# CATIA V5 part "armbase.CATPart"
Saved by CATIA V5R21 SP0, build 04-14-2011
Part number: armbase
Bounding box of the stored display mesh (mm): x -36 to 36, y -57.294 to 35, z 0 to 84.554
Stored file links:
  F:\教程\Robotic_Arm_Arduino_Kinect\机械臂CAD\Arm_Detailed_Design\armbase.CATPart
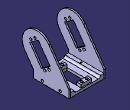
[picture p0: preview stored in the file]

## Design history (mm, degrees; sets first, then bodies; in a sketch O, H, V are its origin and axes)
Body1 (main body)
  Sketch1 on zx-plane, origin (0, 0, 0), H (-1, 0, 0), V (0, 0, 1)
    point P1 (-33, 0)
    line L1 (-33, 0) -> (-33, 9)
    point P2 (-33, 9)
    line L2 (-33, 9) -> (-26, 9)
    point P3 (-26, 9)
    line L3 (-26, 9) -> (-26, 5)
    point P4 (-26, 5)
    line L4 (-26, 5) -> (0, 5)
    point P5 (0, 5)
    line L5 (-33, 0) -> (0, 0)
    point P6 (0, 5)
    point P7 (26, 5)
    line L6 (26, 5) -> (0, 5)
    point P8 (26, 9)
    line L7 (26, 9) -> (26, 5)
    point P9 (33, 9)
    line L8 (33, 9) -> (26, 9)
    point P10 (33, 0)
    line L9 (33, 0) -> (33, 9)
    point P11 (0, 0)
    line L10 (33, 0) -> (0, 0)
    length L5 = 33
    distance L4 L5 = 5
    distance L2 L4 = 4
    length L2 = 7
    coincidence: P1 H, P5 V, O P11, P5 P6
    vertical: L1 V, L3 V
    horizontal: L2 H, L4 H, L5 H
    symmetry: P5 P6 V, P4 P7 V, L4 L6 V, P3 P8 V, L3 L7 V, P2 P9 V, L2 L8 V, P1 P10 V, L1 L9 V, O P11 V, L5 L10 V
  Pad1: profile Sketch1, direction (0, 1, 0), length 35, mirrored extent
  Fillet1: radius 4, on edge [face of Pad1 from Sketch1.L3 | face of Pad1 from Sketch1.L4]; edge [face of Pad1 from Sketch1.L6 | face of Pad1 from Sketch1.L7]
  Sketch2 on face of Pad1 from Sketch1.L6, origin (0, 0, 5), H (1, 0, 0), V (0, 1, 0)
    line L1 (-10.5, 25) -> (10.5, 25)
    line L2 (10.5, 25) -> (10.5, -15.5)
    line L3 (10.5, -15.5) -> (-10.5, -15.5)
    line L4 (-10.5, -15.5) -> (-10.5, 25)
    circle A1 centre (-5, 29) radius 2.5
    point P5 (-5, 29)
    circle A2 centre (5, 29) radius 2.5
    point P6 (5, 29)
    circle A3 centre (-5, -19.5) radius 2.5
    point P7 (-5, -19.5)
    circle A4 centre (5, -19.5) radius 2.5
    point P8 (5, -19.5)
    construction circle A5 centre (0, 15.34) radius 2.8695
    point P9 (0, 15.34)
    axis line L5 (-19.0638, 15.34) -> (25.8227, 15.34)
    length L2 = 40.5
    length L1 = 21
    distance L1 H = 25
    distance L2 V = 10.5
    radius A1 = 2.5
    radius A2 = 2.5
    radius A4 = 2.5
    distance P9 L1 = 9.66
    distance P6 L5 = 13.66
    distance P5 L5 = 13.66
    distance P5 P6 = 10
    distance P7 L5 = 34.84
    distance L5 P8 = 34.84
    distance P8 P7 = 10
    radius A3 = 2.5
    distance P5 V = 5
    distance V P7 = 5
    horizontal: L1 H, L3 H, L5 H
    vertical: L2 V, L4 V
    coincidence: P9 V, L5 P9
  Pocket1: profile Sketch2, direction (0, 0, -1), length 5
  Fillet2: radius 0.5, on edge [face of Pocket1 from Sketch2.L2 | face of Pocket1 from Sketch2.L3]; edge [face of Pocket1 from Sketch2.L1 | face of Pocket1 from Sketch2.L2]; edge [face of Pocket1 from Sketch2.L4 | face of Pocket1 from Sketch2.L1]; edge [face of Pocket1 from Sketch2.L3 | face of Pocket1 from Sketch2.L4]
  Sketch3 on face of Pad1 from Sketch1.L9, origin (-33, 0, 0), H (0, -1, 0), V (0, 0, 1)
    circle A1 centre (-17.5, 4.5) radius 2.5
    point P1 (-17.5, 4.5)
    reference projected line E1 (35, 0) -> (-35, 0) from edge [face of Pad1 from Sketch1.L9 | face of Pad1 from Sketch1.L10]
    circle A2 centre (17.5, 4.5) radius 2.5
    radius A1 = 2.5
    distance P1 E1 = 4.5
    distance V P1 = 17.5
    symmetry: A1 A2 V
  Pocket2: profile Sketch3, direction (1, 0, 0), length 4
  Sketch4 on face of Pad1 from Sketch1.L1, origin (33, 0, 0), H (0, 1, 0), V (0, 0, 1)
    circle A1 centre (-17.5, 4.5) radius 2.5
    point P1 (-17.5, 4.5)
    reference projected line E1 (-35, 0) -> (35, 0) from edge [face of Pad1 from Sketch1.L5 | face of Pad1 from Sketch1.L1]
    circle A2 centre (17.5, 4.5) radius 2.5
    radius A1 = 2.5
    distance P1 V = 17.5
    distance P1 E1 = 4.5
    symmetry: A1 A2 V
  Pocket3: profile Sketch4, direction (-1, 0, 0), length 4
  Sketch5 on face of Pad1, origin (0, 0, 5), H (1, 0, 0), V (0, 1, 0)
    construction circle A1 centre (0, -5.84) radius 32
    point P1 (0, -5.84)
    reference projected line E1 (-26, -35) -> (26, -35) from edge [start face of Pad1 | face of Pad1]
    circle A2 centre (-29, -5.84) radius 1.5
    point P2 (-29, -5.84)
    circle A3 centre (29, -5.84) radius 1.5
    point P3 (29, -5.84)
    distance P1 E1 = 29.16
    radius A1 = 32
    radius A2 = 1.5
    distance P2 P1 = 29
    radius A3 = 1.5
    distance P1 P3 = 29
    coincidence: P1 V
  Pocket4: profile Sketch5, direction (0, 0, -1), length 6, mirrored extent
Body2
  Sketch6 on face of Pad1 from Sketch1.L9, origin (-33, 0, 0), H (0, -1, 0), V (0, 0, 1)
    point P1 (-35, 0)
    line L1 (-35, 0) -> (-35, 15)
    line L2 (-35, 15) -> (5.1504, 72.3406)
    arc A1 centre (28.6357, 55.896) radius 28.6703 from (5.1504, 72.3406) to (52.1211, 39.4514) cw
    line L3 (52.1211, 39.4514) -> (35, 15)
    line L4 (35, 15) -> (35, 0)
    point P7 (35, 0)
    line L5 (35, 0) -> (-35, 0)
    reference projected line E1 (35, 0) -> (35, 9) from edge [start face of Pad1 | face of Pad1 from Sketch1.L9]
    reference projected line E2 (-35, 0) -> (-35, 9) from edge [face of Pad1 from Sketch1.L9 | end face of Pad1]
    circle A2 centre (-17.5, 4.5) radius 2
    point P8 (-17.5, 4.5)
    circle A3 centre (17.5, 4.5) radius 2
    angle L2 L1 = 145
    length L1 = 15
    length L4 = 15
    length L2 = 70
    radius A2 = 2
    distance P8 L5 = 4.5
    distance P8 V = 17.5
    coincidence: P1 H, P7 H, L4 E1, L1 E2
    vertical: L1 V, L4 V
    tangency: A1 L2, L3 A1
    horizontal: L5 H
    parallelism: L3 L2
    symmetry: A2 A3 V
  Pad2: profile Sketch6, direction (-1, 0, 0), length 3
  Sketch7 on end face of Pad2, origin (-36, 0, 0), H (0, -1, 0), V (0, 0, 1)
    line L1 (25.5754, 69.8316) -> (42.7775, 57.7865)
    line L2 (42.7775, 57.7865) -> (19.5477, 24.6108)
    line L3 (19.5477, 24.6108) -> (2.3455, 36.6559)
    line L4 (2.3455, 36.6559) -> (25.5754, 69.8316)
    reference projected line E1 (1.258, 66.7818) -> (-33.1566, 17.6327) from edge [face of Pad2 from Sketch6.L2 | end face of Pad2]
    construction circle A1 centre (28.6357, 55.896) radius 3.7662
    point P5 (28.6357, 55.896)
    reference projected arc E2 centre (28.6357, 55.896) radius 28.6703 from (50.5984, 37.4671) to (6.673, 74.3249) ccw from edge [face of Pad2 from Sketch6.A1 | end face of Pad2]
    circle A2 centre (32.375, 69.9535) radius 2.5
    point P6 (32.375, 69.9535)
    circle A3 centre (40.5665, 64.2178) radius 2.5
    point P7 (40.5665, 64.2178)
    axis line L5 (44.6915, 44.6536) -> (17.7883, 63.4915)
    circle A4 centre (4.5565, 30.2246) radius 2.5
    point P10 (4.5565, 30.2246)
    circle A5 centre (12.7481, 24.4889) radius 2.5
    point P11 (12.7481, 24.4889)
    length L1 = 21
    length L2 = 40.5
    distance P5 L2 = 10.5
    distance P5 L1 = 9.66
    radius A2 = 2.5
    radius A3 = 2.5
    distance P6 L5 = 13.66
    distance P7 L5 = 13.66
    distance P6 P7 = 10
    distance P6 L4 = 5.5
    radius A4 = 2.5
    radius A5 = 2.5
    distance P10 P11 = 10
    length L5 = 32.8428
    distance P11 L5 = 34.84
    distance P10 L4 = 5.5
    distance L5 P10 = 34.84
    parallelism: L4 L2, L1 L3, L4 E1, L5 L1
    perpendicularity: L1 L2
    concentricity: A1 E2
    coincidence: L5 P5
  Pocket5: profile Sketch7, direction (1, 0, 0), length 5
  Fillet3: radius 0.5, on edge [face of Pocket5 from Sketch7.L3 | face of Pocket5 from Sketch7.L4]; edge [face of Pocket5 from Sketch7.L2 | face of Pocket5 from Sketch7.L3]; edge [face of Pocket5 from Sketch7.L1 | face of Pocket5 from Sketch7.L2]; edge [face of Pocket5 from Sketch7.L4 | face of Pocket5 from Sketch7.L1]
  Sketch8 on face of Pad1 from Sketch1.L1, origin (33, 0, 0), H (0, 1, 0), V (0, 0, 1)
    projected line E1 (35, 0) -> (-35, 0) from edge [start face of Pad2 | face of Pad2 from Sketch6.L5]
    projected line E2 (-35, 0) -> (-35, 15) from edge [start face of Pad2 | face of Pad2 from Sketch6.L4]
    projected line E3 (-35, 15) -> (-52.1211, 39.4514) from edge [start face of Pad2 | face of Pad2 from Sketch6.L3]
    projected arc E4 centre (-28.6357, 55.896) radius 28.6703 from (-5.1504, 72.3406) to (-52.1211, 39.4514) ccw from edge [start face of Pad2 | face of Pad2 from Sketch6.A1]
    projected line E5 (-5.1504, 72.3406) -> (35, 15) from edge [start face of Pad2 | face of Pad2 from Sketch6.L2]
    projected line E6 (35, 15) -> (35, 0) from edge [start face of Pad2 | face of Pad2 from Sketch6.L1]
    projected arc E7 centre (-25.6981, 69.1352) radius 0.5 from (-25.2886, 69.422) to (-25.9849, 69.5448) ccw from edge [face of Fillet3 | start face of Pad2]
    projected line E8 (-25.9849, 69.5448) -> (-42.368, 58.0733) from edge [start face of Pad2 | face of Pocket5 from Sketch7.L1]
    projected arc E9 centre (-42.0812, 57.6637) radius 0.5 from (-42.368, 58.0733) to (-42.4908, 57.3769) ccw from edge [face of Fillet3 | start face of Pad2]
    projected line E10 (-42.4908, 57.3769) -> (-19.8345, 25.0204) from edge [start face of Pad2 | face of Pocket5 from Sketch7.L2]
    projected arc E11 centre (-19.4249, 25.3072) radius 0.5 from (-19.8345, 25.0204) to (-19.1381, 24.8976) ccw from edge [face of Fillet3 | start face of Pad2]
    projected line E12 (-19.1381, 24.8976) -> (-2.7551, 36.3691) from edge [start face of Pad2 | face of Pocket5 from Sketch7.L3]
    projected arc E13 centre (-3.0419, 36.7787) radius 0.5 from (-2.7551, 36.3691) to (-2.6323, 37.0655) ccw from edge [face of Fillet3 | start face of Pad2]
    projected line E14 (-2.6323, 37.0655) -> (-25.2886, 69.422) from edge [start face of Pad2 | face of Pocket5 from Sketch7.L4]
    projected circle E15 centre (-32.375, 69.9535) radius 2.5 from edge [face of Pocket5 from Sketch7.A2 | start face of Pad2]
    projected circle E16 centre (-40.5665, 64.2178) radius 2.5 from edge [face of Pocket5 from Sketch7.A3 | start face of Pad2]
    projected circle E17 centre (-4.5565, 30.2246) radius 2.5 from edge [face of Pocket5 from Sketch7.A4 | start face of Pad2]
    projected circle E18 centre (-12.7481, 24.4889) radius 2.5 from edge [face of Pocket5 from Sketch7.A5 | start face of Pad2]
    circle A1 centre (-17.5, 4.5) radius 2.5
    point P29 (-17.5, 4.5)
    circle A2 centre (17.5, 4.5) radius 2.5
    radius A1 = 2.5
    distance P29 E1 = 4.5
    distance P29 V = 17.5
    symmetry: A1 A2 V
  Pad3: profile Sketch8, direction (1, 0, 0), length 3
Body3
  Sketch9 on face of Pad1, origin (0, 0, 5), H (1, 0, 0), V (0, 1, 0)
    point P1 (-10.5, 33)
    line L1 (-10.5, 33) -> (10.5, 33)
    line L2 (10.5, 33) -> (10.5, 25)
    line L3 (10.5, 25) -> (-10.5, 25)
    line L4 (-10.5, 25) -> (-10.5, 33)
    point P2 (10.5, 33)
    point P3 (10.5, 25)
    point P4 (-10.5, 25)
    circle A1 centre (5, 29) radius 2.5
    circle A2 centre (-5, 29) radius 2.5
    reference projected circle E1 centre (5, 29) radius 2.5 from edge [face of Pad1 from Sketch1.L4 | face of Pocket1 from Sketch2.A2]
    reference projected circle E2 centre (-5, 29) radius 2.5 from edge [face of Pad1 from Sketch1.L6 | face of Pocket1 from Sketch2.A1]
    reference projected line E3 (10.5, 25) -> (-10.5, 25) from edge [face of Pad1 | face of Pocket1 from Sketch2.L1]
    axis line L5 (51.9835, 4.75) -> (-25.6214, 4.75)
    point P9 (-10.5, -23.5)
    point P10 (10.5, -23.5)
    point P11 (10.5, -15.5)
    point P12 (-10.5, -15.5)
    line L6 (-10.5, -23.5) -> (10.5, -23.5)
    line L7 (10.5, -23.5) -> (10.5, -15.5)
    line L8 (10.5, -15.5) -> (-10.5, -15.5)
    line L9 (-10.5, -15.5) -> (-10.5, -23.5)
    circle A3 centre (5, -19.5) radius 2.5
    circle A4 centre (-5, -19.5) radius 2.5
    length L2 = 8
    length L1 = 21
    distance V L2 = 10.5
    distance L5 L3 = 20.25
    horizontal: L1 H, L3 H, L5 H
    vertical: L2 V, L4 V
    coincidence: A1 E1, A2 E2, L3 E3
    symmetry: P1 P9 L5, P2 P10 L5, P3 P11 L5, P4 P12 L5, L1 L6 L5, L2 L7 L5, L3 L8 L5, L4 L9 L5, A1 A3 L5, A2 A4 L5
  Pad4: profile Sketch9, direction (0, 0, 1), length 6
